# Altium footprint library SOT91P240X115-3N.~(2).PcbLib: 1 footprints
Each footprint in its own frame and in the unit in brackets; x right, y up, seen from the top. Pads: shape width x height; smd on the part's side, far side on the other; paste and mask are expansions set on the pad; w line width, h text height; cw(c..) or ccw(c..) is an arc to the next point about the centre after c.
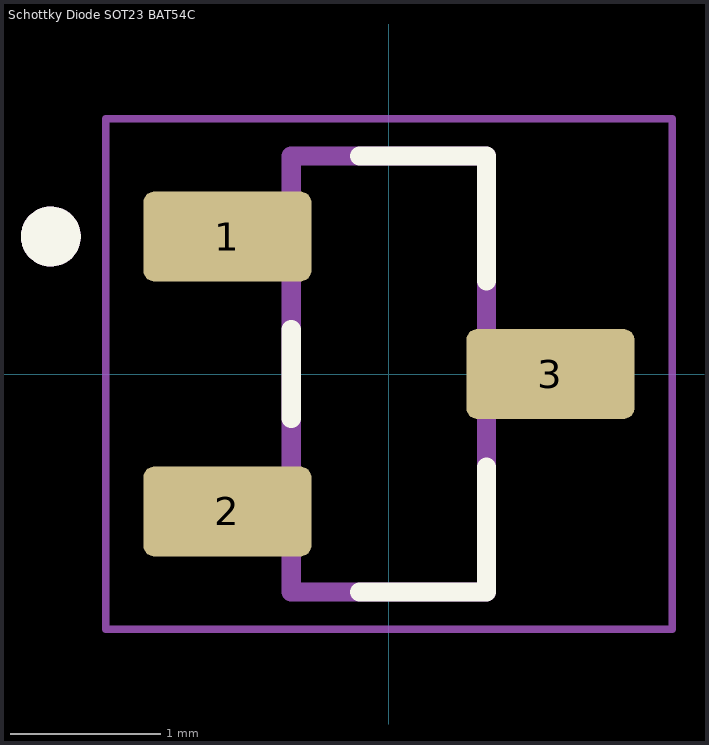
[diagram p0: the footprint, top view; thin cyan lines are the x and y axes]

## Schottky Diode SOT23 BAT54C [mm]
height 1.15
pads (3):
  rrect25% 1.12x0.6 smd: 1(-1.075,0.915) 2(-1.075,-0.915) 3(1.075,0)
Top Overlay:
  circle w0.2: c-2.25,0.915 r0.1
  lines w0.127: -0.65,-0.295 -0.65,0.295 ; -0.195,-1.45 0.65,-1.45 0.65,-0.62 ; -0.195,1.45 0.65,1.45 0.65,0.62
Assembly Top:
  circle w0.2: c-2.25,0.915 r0.1
  lines w0.127: -0.65,-1.45 -0.65,1.45 0.65,1.45 0.65,-1.45 -0.65,-1.45
Courtyard Top:
  lines w0.05: -1.885,-1.7 -1.885,1.7 1.885,1.7 1.885,-1.7 -1.885,-1.7
3D body "step_temp.STEP": height 1.14, standoff 0, extent -1.2,-1.45 1.2,1.45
